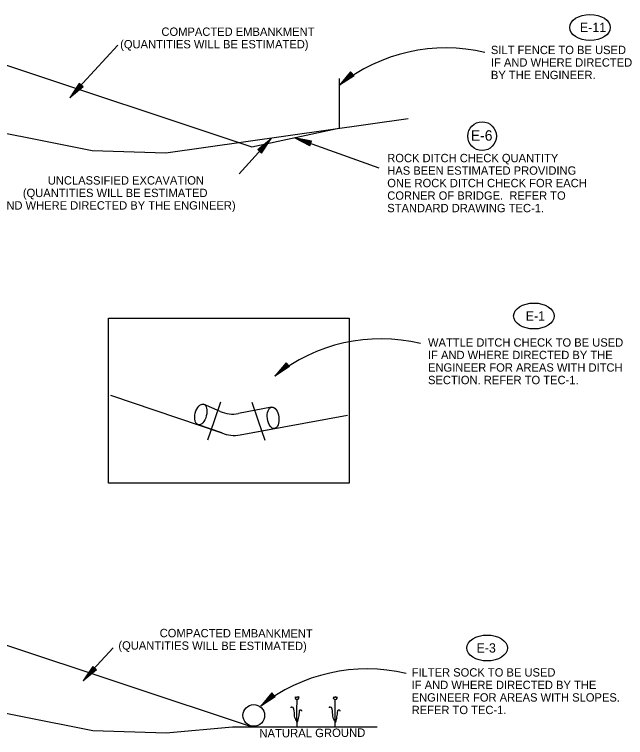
# Model space of a CAD drawing. Extents: x 1929624 to 1932070, y 596315 to 605533.
# Drawn here: x 1931116 to 1931556, y 604928 to 605448 of the extents above; entities that cross this region are included whole.
import ezdxf

# ---------------------------------------------------------------- set-up
doc = ezdxf.new("R2010")
doc.units = 0
for name, color, linetype in [('Default', 7, 'Continuous'), ('R_Border', 7, 'Continuous'), ('R_Draft', 7, 'Continuous')]:
    doc.layers.add(name, color=color, linetype=linetype)

msp = doc.modelspace()

# ---------------------------------------------------------------- linework, layer by layer
at = {"layer": 'Default'}
for p, q in [((1931052.26, 605431.37), (1931287.27, 605353.24)), ((1931190.75, 605426.41), (1931157.25, 605389.86)), ((1931358.35, 605407.12), (1931350.37, 605397.54)), ((1931360.83, 605404.34), (1931350.37, 605397.54)), ((1931358.58, 605406.86), (1931351.93, 605398.89)), ((1931360.61, 605404.57), (1931351.93, 605398.89)), ((1931358.78, 605406.63), (1931353.49, 605400.32)), ((1931360.38, 605404.8), (1931353.49, 605400.32)), ((1931358.97, 605406.42), (1931355.02, 605401.69)), ((1931360.19, 605405.01), (1931355.02, 605401.69)), ((1931359.18, 605406.16), (1931356.57, 605403.06)), ((1931359.99, 605405.25), (1931356.57, 605403.06)), ((1931359.4, 605405.93), (1931358.15, 605404.44)), ((1931359.79, 605405.51), (1931358.15, 605404.44)), ((1931360.83, 605404.34), (1931358.35, 605407.12)), ((1931163.13, 605398.8), (1931156.22, 605388.43)), ((1931163.38, 605398.61), (1931157.6, 605389.93)), ((1931163.64, 605398.37), (1931159.06, 605391.58)), ((1931163.81, 605398.15), (1931160.43, 605393.08)), ((1931164.04, 605397.98), (1931161.79, 605394.6)), ((1931165.84, 605396.34), (1931163.13, 605398.8)), ((1931164.27, 605397.75), (1931163.19, 605396.14)), ((1931165.84, 605396.34), (1931156.22, 605388.43)), ((1931165.65, 605396.53), (1931157.6, 605389.93)), ((1931165.37, 605396.75), (1931159.06, 605391.58)), ((1931165.14, 605396.96), (1931160.43, 605393.08)), ((1931164.89, 605397.18), (1931161.79, 605394.6)), ((1931164.71, 605397.43), (1931163.19, 605396.14)), ((1931287.27, 605353.24), (1931348.62, 605366.31)), ((1931278.04, 605333.71), (1931301.13, 605359.09)), ((1931291.51, 605351.17), (1931301.13, 605359.09)), ((1931291.71, 605350.98), (1931299.75, 605357.58)), ((1931291.99, 605350.76), (1931298.29, 605355.94)), ((1931293.72, 605349.14), (1931298.29, 605355.94)), ((1931293.98, 605348.9), (1931299.75, 605357.58)), ((1931294.23, 605348.71), (1931301.13, 605359.09)), ((1931378.79, 605337.87), (1931317.94, 605359.78)), ((1931328.92, 605353.88), (1931317.94, 605359.78)), ((1931330.16, 605357.32), (1931317.94, 605359.78)), ((1931329.02, 605354.14), (1931319.86, 605359.07)), ((1931330.08, 605357.03), (1931319.86, 605359.07)), ((1931329.95, 605356.69), (1931321.93, 605358.34)), ((1931329.11, 605354.47), (1931321.93, 605358.34)), ((1931329.23, 605354.76), (1931323.84, 605357.65)), ((1931329.82, 605356.45), (1931323.84, 605357.65)), ((1931329.75, 605356.17), (1931325.77, 605356.97)), ((1931329.34, 605355.08), (1931325.77, 605356.97)), ((1931329.63, 605355.87), (1931327.73, 605356.26)), ((1931329.49, 605355.34), (1931327.73, 605356.26)), ((1931328.92, 605353.88), (1931330.16, 605357.32)), ((1931291.51, 605351.17), (1931294.23, 605348.71)), ((1931292.21, 605350.55), (1931296.93, 605354.44)), ((1931292.47, 605350.33), (1931295.56, 605352.91)), ((1931292.65, 605350.08), (1931294.17, 605351.37)), ((1931293.09, 605349.75), (1931294.17, 605351.37)), ((1931293.31, 605349.53), (1931295.56, 605352.91)), ((1931293.55, 605349.36), (1931296.93, 605354.44)), ((1931311.87, 605197.87), (1931303.89, 605188.29)), ((1931314.35, 605195.09), (1931303.89, 605188.29)), ((1931312.1, 605197.61), (1931305.45, 605189.64)), ((1931314.13, 605195.32), (1931305.45, 605189.64)), ((1931312.3, 605197.38), (1931307.01, 605191.07)), ((1931313.9, 605195.55), (1931307.01, 605191.07)), ((1931312.49, 605197.16), (1931308.54, 605192.43)), ((1931313.71, 605195.76), (1931308.54, 605192.43)), ((1931312.7, 605196.91), (1931310.09, 605193.81)), ((1931313.51, 605195.99), (1931310.09, 605193.81)), ((1931312.92, 605196.67), (1931311.67, 605195.19)), ((1931313.31, 605196.25), (1931311.67, 605195.19)), ((1931314.35, 605195.09), (1931311.87, 605197.87)), ((1931185.65, 605174.58), (1931265.69, 605147.44)), ((1931278.96, 605145.9), (1931356.18, 605160.27)), ((1931052.52, 605014.09), (1931287.53, 604935.97)), ((1931187.48, 604992.77), (1931166.93, 604970.35)), ((1931172.81, 604979.29), (1931165.9, 604968.92)), ((1931175.52, 604976.83), (1931165.9, 604968.92)), ((1931173.06, 604979.1), (1931167.28, 604970.43)), ((1931175.33, 604977.02), (1931167.28, 604970.43)), ((1931173.32, 604978.86), (1931168.74, 604972.07)), ((1931175.05, 604977.24), (1931168.74, 604972.07)), ((1931173.49, 604978.64), (1931170.11, 604973.57)), ((1931174.82, 604977.46), (1931170.11, 604973.57)), ((1931173.72, 604978.47), (1931171.47, 604975.09)), ((1931174.57, 604977.68), (1931171.47, 604975.09)), ((1931175.52, 604976.83), (1931172.81, 604979.29)), ((1931173.95, 604978.25), (1931172.87, 604976.64)), ((1931174.39, 604977.92), (1931172.87, 604976.64)), ((1931301.66, 604960.35), (1931293.68, 604950.77)), ((1931304.14, 604957.57), (1931293.68, 604950.77)), ((1931301.89, 604960.09), (1931295.24, 604952.12)), ((1931303.92, 604957.8), (1931295.24, 604952.12)), ((1931302.09, 604959.86), (1931296.81, 604953.55)), ((1931303.7, 604958.03), (1931296.81, 604953.55)), ((1931302.28, 604959.65), (1931298.33, 604954.92)), ((1931303.5, 604958.24), (1931298.33, 604954.92)), ((1931302.49, 604959.39), (1931299.88, 604956.29)), ((1931303.3, 604958.47), (1931299.88, 604956.29)), ((1931302.71, 604959.16), (1931301.46, 604957.67)), ((1931303.1, 604958.73), (1931301.46, 604957.67)), ((1931304.14, 604957.57), (1931301.66, 604960.35))]:
    msp.add_line(p, q, dxfattribs=at)
for centre in [(1931426.56, 605302.62), (1931380.08, 605093.35), (1931369.87, 604855.83)]:
    msp.add_arc(centre, 121.72, 76.502, 128.7522, dxfattribs=at)
at = {"layer": 'R_Border'}
for p, q in [((1931350.33, 605366.61), (1931350.33, 605402.3)), ((1931264.42, 605162.86), (1931252.48, 605168.11)), ((1931301.51, 605165.95), (1931277.7, 605161.32)), ((1931265.69, 605147.44), (1931248.07, 605153.4)), ((1931278.96, 605145.9), (1931303.59, 605150.48))]:
    msp.add_line(p, q, dxfattribs=at)
for points in [[(1930830.08, 605440.25), (1931067.62, 605371.32), (1931172.51, 605350.45), (1931225.36, 605348.85), (1931399.81, 605373.56)], [(1931264.74, 605169.59), (1931260.18, 605156.14), (1931255.41, 605142.09)], [(1931287.25, 605169.59), (1931291.81, 605156.14), (1931296.58, 605142.09)], [(1930830.34, 605022.98), (1931067.88, 604954.04), (1931172.78, 604933.18), (1931225.62, 604931.58), (1931273.23, 604935.95), (1931377.44, 604935.97)]]:
    msp.add_lwpolyline(points, dxfattribs=at)
msp.add_lwpolyline([(1931184.2, 605229.88), (1931357.2, 605229.88), (1931357.2, 605111.18), (1931184.2, 605111.18)], close=True, dxfattribs=at)
for centre, radius in [((1931452.9, 605360.89), 10.32), ((1931288.62, 604944.14), 7.8)]:
    msp.add_circle(centre, radius, dxfattribs=at)
for centre in [(1931273.53, 605183.4), (1931274.79, 605167.98), (1931274.79, 605167.98)]:
    msp.add_arc(centre, 22.47, 246.0784, 280.6856, dxfattribs=at)
for centre, major_axis, ratio in [((1931530.51, 605439.11), (14.6, 0), 0.638788), ((1931490.17, 605231.5), (14.6, 0), 0.638788), ((1931250.55, 605160.66), (-1.93, -7.45), 0.531792), ((1931302.55, 605158.21), (1.04, -7.73), 0.531792), ((1931456.54, 604992.64), (14.6, 0), 0.638788)]:
    msp.add_ellipse(centre, major_axis=major_axis, ratio=ratio, dxfattribs=at)
at = {"layer": 'R_Draft'}
for points in [[(1931318.45, 604957.55), (1931318.43, 604957.59), (1931318.92, 604956.89), (1931319.5, 604957.7), (1931319.93, 604956.91), (1931320.36, 604957.7), (1931320.76, 604956.92), (1931321.18, 604957.43)], [(1931345.93, 604957.56), (1931345.91, 604957.6), (1931346.4, 604956.9), (1931346.99, 604957.71), (1931347.41, 604956.92), (1931347.84, 604957.71), (1931348.25, 604956.93), (1931348.66, 604957.44)]]:
    msp.add_lwpolyline(points, dxfattribs=at)
for centre in [(1931319.79, 604957.04), (1931347.27, 604957.05)]:
    msp.add_arc(centre, 1.46, 161.1287, 15.4588, dxfattribs=at)
for points in [[(1931319.61, 604955.72), (1931319.53, 604952.61), (1931319.53, 604935.92)], [(1931347.09, 604955.73), (1931347.02, 604952.62), (1931347.02, 604935.93)], [(1931319.53, 604939.89), (1931318.58, 604941.72), (1931317.87, 604945.93), (1931316.04, 604950.14), (1931315.48, 604949.99), (1931315.32, 604949.51)], [(1931347.02, 604939.9), (1931346.06, 604941.73), (1931345.35, 604945.94), (1931343.52, 604950.15), (1931342.96, 604950), (1931342.8, 604949.52)], [(1931319.53, 604938.7), (1931320.09, 604939.57), (1931320.81, 604942.12), (1931321.44, 604946.33), (1931321.99, 604948.09), (1931322.48, 604948.09), (1931323.03, 604947.76), (1931323.03, 604947.29)], [(1931347.02, 604938.71), (1931347.57, 604939.58), (1931348.29, 604942.13), (1931348.92, 604946.34), (1931349.47, 604948.1), (1931349.96, 604948.1), (1931350.51, 604947.77), (1931350.51, 604947.3)]]:
    msp.add_spline(points, degree=3, dxfattribs=at)

# ---------------------------------------------------------------- texts
at = {"layer": 'Default'}
for s, p in [('COMPACTED EMBANKMENT', (1931222.2, 605433.04)), ('(QUANTITIES WILL BE ESTIMATED)', (1931192.52, 605424.04)), ('SILT FENCE TO BE USED ', (1931459.23, 605419.92)), ('IF AND WHERE DIRECTED', (1931459.23, 605410.92)), ('BY THE ENGINEER. ', (1931459.23, 605401.92)), ('ROCK DITCH CHECK QUANTITY', (1931384.67, 605342.14)), ('HAS BEEN ESTIMATED PROVIDING', (1931384.67, 605333.14)), ('UNCLASSIFIED EXCAVATION', (1931140.47, 605326.06)), ('ONE ROCK DITCH CHECK FOR EACH', (1931384.67, 605324.14)), ('(QUANTITIES WILL BE ESTIMATED', (1931122.52, 605317.06)), ('CORNER OF BRIDGE.  REFER TO ', (1931384.67, 605315.14)), ('IF AND WHERE DIRECTED BY THE ENGINEER)', (1931095.96, 605308.06)), ('STANDARD DRAWING TEC-1.', (1931384.67, 605306.14)), ('WATTLE DITCH CHECK TO BE USED', (1931413.99, 605209.45)), ('IF AND WHERE DIRECTED BY THE', (1931413.99, 605200.45)), ('ENGINEER FOR AREAS WITH DITCH ', (1931413.99, 605191.45)), ('SECTION. REFER TO TEC-1.', (1931413.99, 605182.45)), ('FILTER SOCK TO BE USED', (1931402.23, 604972.08)), ('IF AND WHERE DIRECTED BY THE', (1931402.23, 604963.08)), ('ENGINEER FOR AREAS WITH SLOPES. ', (1931402.23, 604954.08)), ('REFER TO TEC-1.', (1931402.23, 604945.08))]:
    msp.add_text(s, height=6, dxfattribs=at).set_placement(p)
for s, height, rotation, p in [('COMPACTED EMBANKMENT', 6, 359.8271, (1931220.95, 605000.41)), ('(QUANTITIES WILL BE ESTIMATED)', 6, 359.8271, (1931191.25, 604991.5)), ('NATURAL GROUND', 6.075, 0.3856, (1931292.66, 604928.22))]:
    msp.add_text(s, height=height, rotation=rotation, dxfattribs=at).set_placement(p)
at = {"layer": 'R_Border'}
for s, p in [('E-11', (1931523.29, 605435.83)), ('E-1', (1931484.26, 605228.22)), ('E-3', (1931448.92, 604989.37))]:
    msp.add_text(s, height=6.663, rotation=360, dxfattribs=at).set_placement(p)
msp.add_text('E-6 ', height=7.499, dxfattribs=at).set_placement((1931444.78, 605357.63))

doc.saveas('drawing.dxf')
